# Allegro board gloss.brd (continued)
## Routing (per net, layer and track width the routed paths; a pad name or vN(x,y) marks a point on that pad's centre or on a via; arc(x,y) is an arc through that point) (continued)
MEMORY.RA12: length 159.2
  TOP w0.15: 115.23,90.16 115.23,89.87 115.08,89.72 U21.19 ; 115.23,90.16 115.23,90.81 115.53,91.1 117.48,91.1 118.55,92.17 118.55,97.7 115.22,101.03 115.22,101.77 ; 115.23,90.16 115.23,90.91 115.12,90.8 115.12,86.3 116.49,84.94 116.49,81.44 116.39,81.34 116.39,78.79 114.48,76.89 U20.19 ; U23.19 114.48,113.17 ; 114.48,113.17 115,112.65 115,106.97 115.12,106.86 115.12,105.54 115.22,105.44 115.22,103.38 115.12,103.28 115.12,101.87 115.22,101.77 ; 114.48,113.17 114.19,112.87 113.35,112.87 112.58,113.64 112.58,116.57 111.58,117.57 103.79,117.57 102.42,116.2 102.42,113.8 99.98,111.36 v1(95.48,111.36) ; 91,100.07 91,101.03 ; 91,100.07 v1(90.08,100.07) ; 91,100.07 91,93.97 91.12,93.86 91.12,91.38 90.48,90.75 U17.19 90.48,83.03 v1(90.92,82.6) ; 91,101.03 90.48,101.56 U18.19 ; 91,101.03 93.45,101.03 93.65,101.23 93.65,105.71 94.44,106.5 94.44,110.63 v1(93.71,111.36) 92.9,111.36 90.48,113.77 U19.19 ; 115.22,101.77 114.94,101.77 U22.19 ; v1(89.45,82.6) 89.45,81.78 89.73,81.5 89.73,76.37 89.89,76.22 U16.19 ; v1(63.81,99.11) 64.56,98.36 66.85,98.36 67.34,97.87 67.34,97.08 66.72,96.46 U5.62
  BOTTOM w0.15: v1(63.81,99.11) 84.52,99.11 85.47,100.07 v1(90.08,100.07) ; v1(95.48,111.36) v1(93.71,111.36) ; v1(89.45,82.6) v1(90.92,82.6)
MEMORY.RA13: length 180.9
  TOP w0.15: 117.55,87.94 118.85,89.24 118.85,102.05 117.2,103.7 116.49,103.7 ; 117.55,87.94 116.26,87.94 115.75,88.44 U21.18 ; 117.55,87.94 117.55,78.67 115.75,76.89 U20.18 ; 92.49,86.57 92.91,86.57 93.55,87.2 93.55,100.3 ; 92.49,86.57 92.39,86.47 92.39,78.72 92.5,78.62 92.5,77.62 91.75,76.89 U16.18 ; 92.49,86.57 92.15,86.57 91.75,86.97 U17.18 ; 94.74,112.26 100.4,112.26 101.15,113.01 101.15,116.3 101.03,116.41 101.03,117.16 102.18,118.3 113.98,118.3 115.75,116.53 U23.18 115.75,111.35 116.49,110.62 116.49,106.94 116.39,106.84 116.39,103.8 116.49,103.7 ; 94.74,112.26 94.74,105.35 94.44,105.06 94.44,101.2 93.55,100.3 ; 94.74,112.26 93.41,112.26 91.75,113.91 U19.18 ; U18.18 92.36,102.22 92.49,102.35 92.49,103.41 v1(92.92,103.84) ; 116.49,103.7 116.49,102.35 116.36,102.22 U22.18 ; 93.55,100.3 v1(92.79,100.3) ; U5.61 64.13,95.19 62.73,96.59 62.73,103.62 62.22,104.13 v1(61.17,104.13)
  BOTTOM w0.15: v1(92.92,103.84) 92.92,100.43 v1(92.79,100.3) 92.79,97.37 92.15,96.73 91.45,96.73 90.81,97.37 90.81,100.41 88.66,102.57 61.68,102.57 61.17,103.08 v1(61.17,104.13)
MEMORY.RA14: length 163.2
  TOP w0.15: v1(91.75,103.91) U19.15 91.75,106.17 93.29,107.7 v1(93.71,107.7) ; U21.15 v1(115.75,82.73) ; U16.15 v1(91.75,68.4) ; U23.15 v1(115.75,107.25) ; v1(62,103.31) 62,96.08 64.16,93.92 U5.60 ; v1(91.75,97.46) U18.15 91.75,90.97 91.12,90.33 91.12,85.77 91.75,85.14 U17.15 v1(91.75,78.16) ; U20.15 v1(115.75,68.4) ; U22.15 v1(115.75,94.4)
  BOTTOM w0.15: 91.75,103.11 v1(91.75,103.91) ; 91.75,103.11 v1(91.75,97.46) ; 91.75,103.11 62.2,103.11 v1(62,103.31) ; v1(115.75,68.4) v1(115.75,82.73) v1(115.75,94.4) v1(115.75,107.25) 115.75,112.68 114.1,114.33 98.18,114.33 97.68,113.83 97.68,110.36 95.01,107.7 v1(93.71,107.7) ; v1(91.75,78.16) v1(91.75,68.4)
MEMORY.RA15: length 196.8
  TOP w0.15: v1(73.26,72.23) 81.38,72.23 85.19,68.42 85.19,67.97 ; 113.97,66.63 113.97,65.3 111.47,62.8 87.68,62.8 84.77,65.7 84.77,67.97 85.19,67.97 ; 113.97,66.63 114.34,66.63 U20.14 ; 113.97,66.63 113.97,65.59 113.85,65.7 113.85,77.3 113.97,77.41 113.97,78.44 114.48,78.96 U21.14 v1(114.48,81.8) 114.48,86.95 113.97,87.47 113.97,88.53 113.85,88.64 113.85,90.83 114.48,91.47 U22.14 ; U19.14 91.08,105.78 91.11,105.8 v1(91.11,107.4) ; U5.58 v1(60.31,91.38) ; v1(108.63,108.56) 112.97,108.56 114.48,107.05 U23.14 v1(114.48,103.91) ; 85.19,67.97 85.8,67.97 86.04,67.72 86.04,65.81 86.34,65.51 89.88,65.51 90.48,66.12 U16.14 v1(90.48,69.27) ; v1(90.48,78.16) U17.14 90.48,81.72 90.19,82.02 90.19,86.19 89.85,86.52 89.85,90.86 90.48,91.49 U18.14
  BOTTOM w0.15: v1(91.11,107.4) 91.84,106.67 101.48,106.67 103.38,108.56 v1(108.63,108.56) ; v1(73.26,72.23) 73.26,78.3 67.16,84.4 66.53,84.4 60.31,90.62 v1(60.31,91.38) ; v1(90.48,69.27) v1(90.48,78.16) ; v1(114.48,103.91) v1(114.48,81.8)
MEMORY.RCS0: length 54.5
  TOP w0.15: U5.51 v1(61.66,81.71) ; U17.6 v1(80.33,81.4) ; v1(71.63,65.35) 80.19,65.35 80.33,65.48 U16.6 v1(80.33,69.77)
  BOTTOM w0.15: v1(80.33,69.77) 80.33,70.58 79.81,71.1 79.81,80.06 80.33,80.58 v1(80.33,81.4) ; v1(61.66,81.71) 68.83,81.71 71.63,78.92 v1(71.63,65.35)
MEMORY.RCS1: length 41.2
  TOP w0.15: U19.6 80.33,104.52 79.22,103.41 78.56,103.41 78.31,103.15 78.31,100.69 78.16,100.54 78.16,97.34 v1(80.33,95.17) U18.6 ; v1(62.51,89.81) 60.39,87.69 U5.50
  BOTTOM w0.15: v1(80.33,95.17) 67.87,95.17 v1(62.51,89.81)
MEMORY.RCS2: length 79.7
  TOP w0.15: v1(95.25,64.13) 95.25,66.88 99.44,71.07 102.13,71.07 v1(102.86,70.34) 104.33,68.87 U20.6 ; U21.6 v1(104.33,81.9) ; U5.49 v1(59.12,80.85)
  BOTTOM w0.15: v1(59.12,80.85) 70.8,69.16 70.8,65.02 71.69,64.13 v1(95.25,64.13) ; v1(104.33,81.9) 102.86,80.43 v1(102.86,70.34)
MEMORY.RCS3: length 65.8
  TOP w0.15: U22.6 104.33,94.94 v1(104.13,95.13) 105.17,96.17 105.17,99.67 105.06,99.79 105.06,101.06 104.96,101.16 104.96,103.44 104.33,104.07 U23.6 ; U5.48 57.85,86.34 62.16,90.65 v1(68.87,90.65)
  BOTTOM w0.15: v1(68.87,90.65) 94.74,90.65 97.4,93.31 97.4,94.11 98.42,95.13 v1(104.13,95.13)
MEMORY.RD0: length 187.2
  TOP w0.15: v1(92.49,94.4) v1(92.49,87.6) ; v1(101.98,68.7) 102.79,68.7 103.69,67.8 103.69,65.72 103.79,65.62 103.79,65.59 104.09,65.59 ; U18.7 v1(81.59,95.22) ; v1(59.36,93.15) 56.58,95.92 U5.81 ; U22.7 v1(105.59,94.4) ; v1(84.15,64.86) 83.58,64.29 81.87,64.29 81.59,64.56 ; 81.59,64.56 U16.7 ; 81.59,64.56 71.34,64.56 70.59,65.31 70.59,68.7 v1(72.36,70.46) ; 104.09,65.59 104.09,64.92 103.29,64.13 v1(99.11,64.13) ; 104.09,65.59 104.8,65.59 105.59,66.4 U20.7
  BOTTOM w0.15: v1(105.59,94.4) 100.63,89.44 83.91,89.44 82.13,87.66 82.13,86.92 82.53,86.53 92.49,86.53 ; v1(81.59,95.22) 81.59,94.41 82.34,93.67 91.75,93.67 v1(92.49,94.4) ; v1(84.15,64.86) 98.38,64.86 v1(99.11,64.13) ; v1(101.98,68.7) 101.98,83.1 98.55,86.53 92.49,86.53 ; v1(59.36,93.15) 59.36,91.04 66.6,83.8 67.28,83.8 72.36,78.72 v1(72.36,70.46) ; 92.49,86.53 v1(92.49,87.6)
MEMORY.RD1: length 201.1
  TOP w0.15: v1(55.31,95.96) U5.82 ; U22.10 109.41,93.44 111.09,95.13 v1(117.52,95.13) ; v1(84.99,95.22) 85.41,94.81 U18.10 ; U16.10 85.41,65.56 87.56,63.4 108.39,63.4 v1(109.41,64.41) U20.10
  BOTTOM w0.15: v1(84.99,95.22) 84.26,95.96 58.32,95.96 ; 58.32,95.96 v1(55.31,95.96) ; 58.32,95.96 58.32,80.52 70.2,68.64 70.2,65.15 71.6,63.75 86.59,63.75 86.94,63.4 108.39,63.4 v1(109.41,64.41) 113.97,64.41 117.52,67.97 v1(117.52,95.13)
MEMORY.RD2: length 166.6
  TOP w0.15: U18.23 v1(85.41,103.91) ; v1(61.66,79.35) 59.47,79.35 57.22,81.61 57.22,86.13 57.31,86.23 57.31,87.29 54.04,90.56 v1(54.04,103.4) U5.83 ; 80.1,73.23 79.85,72.97 74.55,72.97 69.59,77.92 v1(69.59,79.35) ; 80.1,73.23 107.08,73.23 109.41,75.56 U20.23 ; 80.1,73.23 79.69,73.64 79.69,77.16 79.93,77.41 84.6,77.41 85.41,76.61 U16.23 ; U22.23 v1(109.41,100.6)
  BOTTOM w0.15: v1(61.66,79.35) v1(69.59,79.35) ; v1(109.41,100.6) 109.41,99.79 108.58,98.97 97.3,98.97 94.25,102.02 94.25,103.63 93.24,104.65 85.41,104.65 ; 85.41,104.65 85.19,104.86 55.51,104.86 v1(54.04,103.4) ; 85.41,104.65 v1(85.41,103.91)
MEMORY.RD3: length 236.3
  TOP w0.15: U16.26 81.59,74.42 82.48,73.53 104.52,73.53 v1(105.59,74.6) U20.26 ; U5.84 v1(52.77,102.57) ; U22.26 105.59,103.64 104.96,104.27 104.96,106.84 104.86,106.93 104.86,107.82 106.64,109.6 110.48,109.6 111.19,110.31 v1(111.19,116.84) ; U18.26 v1(81.59,100.22)
  BOTTOM w0.15: 113.95,117.14 113.65,116.84 v1(111.19,116.84) ; 113.95,117.14 116.79,114.3 116.79,67.7 116.15,67.06 115.49,67.06 111.55,71 111.55,71.27 107.49,75.33 106.33,75.33 v1(105.59,74.6) ; 113.95,117.14 113.95,117.91 113.55,118.3 57.45,118.3 50.47,111.32 50.47,104.88 v1(52.77,102.57) 53.58,102.57 53.88,102.27 79.55,102.27 v1(81.59,100.22)
MEMORY.RD4: length 126.4
  TOP w0.15: v1(105.6,107.4) U23.7 105.59,104.52 106.11,104 106.11,103.41 106.23,103.3 106.23,96.17 104.86,94.81 104.86,93.94 104.96,93.84 104.96,88.55 105.17,88.34 105.17,82.93 ; U17.7 81.59,78.52 82.41,77.7 85.54,77.7 86.04,77.21 86.04,75.14 85.92,75.03 85.92,74.27 86.32,73.87 102.31,73.87 103.69,75.25 103.69,77.3 103.58,77.41 103.58,79.09 103.69,79.2 103.69,81.36 103.58,81.47 103.58,82.3 104.21,82.93 105.17,82.93 ; 105.17,82.93 105.59,82.51 U21.7 ; U19.7 v1(81.59,107.4) ; U5.1 v1(51.5,111.31)
  BOTTOM w0.15: v1(51.5,111.31) 52.63,112.43 75.16,112.43 79.16,108.43 80.56,108.43 v1(81.59,107.4) 82.93,106.06 104.26,106.06 v1(105.6,107.4)
MEMORY.RD5: length 155.4
  TOP w0.15: v1(66.27,115.93) 51.93,115.93 50.23,114.22 U5.2 ; U19.10 85.41,107.4 v1(85.41,107.4) ; U17.10 v1(85.41,81.4) ; U21.10 v1(109.41,78.66) ; v1(109.35,104.16) 109.41,104.21 U23.10
  BOTTOM w0.15: v1(109.41,78.66) 108.61,79.45 105.06,79.45 ; 105.06,79.45 104.73,79.45 103.59,78.31 103.59,69.22 101.94,67.57 91.07,67.57 88.15,70.5 88.15,71.37 85.41,74.12 v1(85.41,81.4) ; 105.06,79.45 105.06,82.56 103.71,83.91 103.71,85.38 104.5,86.17 108.62,86.17 111.03,88.58 111.03,97.8 110.42,98.41 110.42,103.09 v1(109.35,104.16) 109.35,106.04 107.26,108.13 104.13,108.13 102.37,106.36 86.44,106.36 v1(85.41,107.4) 86.95,108.94 86.95,110.83 85.81,111.97 82.85,111.97 81.2,113.63 68.56,113.63 v1(66.27,115.93)
MEMORY.RD6: length 175.7
  TOP w0.15: U21.23 v1(109.41,88.1) 109.21,87.91 v1(109.21,83.02) ; U17.23 v1(85.41,87.36) ; v1(69.1,114.76) 67.2,116.66 50.74,116.66 48.96,114.88 U5.3 ; U23.23 v1(109.41,116.84) ; U19.23 v1(85.41,113.29)
  BOTTOM w0.15: v1(109.41,88.1) 108.67,88.83 86.88,88.83 v1(85.41,87.36) ; v1(69.1,114.76) 69.57,114.29 85.41,114.29 ; v1(109.21,83.02) 112.15,80.08 112.15,70.84 115.33,67.66 116.09,67.66 116.49,68.06 116.49,112.49 113.44,115.53 109.41,115.53 ; 85.41,114.29 v1(85.41,113.29) ; 85.41,114.29 94.99,114.29 96.23,115.53 109.41,115.53 ; 109.41,115.53 v1(109.41,116.84)
MEMORY.RD7: length 169.4
  TOP w0.15: v1(69.23,116.11) 68.08,117.26 50.1,117.26 47.69,114.85 U5.4 ; 106.11,89.86 105.74,89.86 U21.26 ; 106.11,89.86 106.11,90.69 106.68,91.25 108.2,91.25 108.77,91.82 108.77,93.86 111.53,96.62 v1(112.77,96.62) ; 106.11,89.86 106.11,90.91 106.23,90.8 106.23,88.64 106.11,88.53 v1(106.11,78.42) ; U17.26 81.59,87.36 80.33,86.09 v1(79.59,86.09) ; v1(105.59,116.84) U23.26 v1(105.59,113.43) ; v1(81.59,116.84) U19.26
  BOTTOM w0.15: 81.59,116.11 104.86,116.11 v1(105.59,116.84) ; 81.59,116.11 v1(81.59,116.84) ; 81.59,116.11 v1(69.23,116.11) ; v1(106.11,78.42) 103.89,76.2 103.89,69.05 102.11,67.27 90.85,67.27 87.55,70.58 87.55,71.32 85.9,72.97 83.09,72.97 81.57,74.5 81.57,82.27 79.59,84.25 v1(79.59,86.09) ; v1(112.77,96.62) 112.77,112.54 111.88,113.43 v1(105.59,113.43)
MEMORY.RWE: length 175.1
  TOP w0.15: U16.11 86.67,68.05 90,71.37 v1(93.61,71.37) 103.73,71.37 104.33,70.77 110.38,70.77 110.67,70.47 ; 111.41,92.33 111.13,92.33 U22.11 ; 111.41,92.33 111.31,92.43 111.31,93.74 111.53,93.97 114.88,93.97 115.12,93.72 115.12,91.73 115.45,91.4 117.27,91.4 118.25,92.39 118.25,95.55 115.84,97.96 112.31,97.96 110.16,100.12 110.16,101.03 110.04,101.14 110.04,103.63 110.67,104.27 U23.11 ; 111.41,92.33 111.41,90.88 111.31,90.78 111.31,86.43 112.43,85.31 112.43,82.48 111.19,81.25 111.19,80.42 ; U21.11 110.82,80.42 111.19,80.42 ; 111.19,80.42 111.31,80.31 111.31,71.1 110.67,70.47 ; U19.11 86.67,104.27 87.19,103.75 87.19,103.41 87.31,103.3 87.31,101.18 85.54,99.42 79.39,99.42 78.75,98.78 78.75,98.04 80.03,96.77 86.91,96.77 87.59,97.44 88.21,97.44 88.72,96.93 88.72,94.66 88.32,94.27 87.5,94.27 86.67,93.44 U18.11 86.67,90.97 87.31,90.33 87.31,88.14 87.04,87.88 v1(87.04,81.7) 86.67,81.33 U17.11 ; 110.67,70.47 U20.11 ; U5.56 v1(70.52,88.84)
  BOTTOM w0.15: v1(70.52,88.84) 79.83,88.84 81.36,87.32 81.36,86.69 82.37,85.67 86.46,85.67 87.34,84.8 ; 87.34,84.8 87.04,84.5 v1(87.04,81.7) ; 87.34,84.8 89.8,84.8 93.61,80.99 v1(93.61,71.37)
MRD: length 38.8
  BOTTOM w0.15: J1.46 13.17,53.52 13.43,53.78 38.73,53.78 43.41,58.46 43.41,60.23 U2.9
MWR: length 44.6
  BOTTOM w0.15: U2.10 47.17,64.19 47.17,60.2 38.47,51.49 13.69,51.49 13.17,50.98 J1.45
N00036_DATA_DAAMP: length 38.4
  TOP w0.15: 83.41,43.17 83.74,43.5 87.08,43.5 87.23,43.66 87.23,44.6 86.44,45.41 U10.5 ; 83.41,43.17 U8.8 ; 83.41,43.17 83.41,41.42 83.27,41.27 81.14,41.27 80.91,41.04 80.91,39.36 ; U8.5 80.91,39.36 ; 80.91,39.36 80.91,37.61 81.05,37.46 84.62,37.46 84.95,37.13 v1(85.76,37.13) 92.4,30.5 L4.2
  BOTTOM w0.15: R7.1 86.83,37 86.83,37.13 ; R6.1 87.44,39.5 86.83,38.88 86.83,37.13 ; 86.83,37.13 v1(85.76,37.13)
N00036_DATA_DAAMP1: length 35.5
  TOP w0.15: L6.2 96.16,11.85 96.16,13.21 95.01,14.35 92.11,14.35 87.25,19.21 v1(84.45,19.21) 83.71,19.21 83.71,19.44 ; U11.5 83.71,19.44 ; 83.71,19.44 83.71,23.25 ; U11.8 83.71,23.25 ; 83.71,23.25 83.71,24.47 84.73,25.48 U13.5
  BOTTOM w0.15: R9.1 86.78,17.08 86.53,17.33 86.53,19.21 ; R8.1 86.78,19.58 86.53,19.32 86.53,19.21 ; 86.53,19.21 v1(84.45,19.21)
N00038_DATA_DAAMP: length 24.8
  TOP w0.15: v1(83.85,39.7) 83.85,38.39 ; 83.85,38.39 85.69,38.39 91.08,33 L3.2 ; 83.85,38.39 83.55,38.09 U8.4
  BOTTOM w0.15: v1(83.85,39.7) 81.17,42.38 77.51,42.38 77.5,42.37 C8.1
N00038_DATA_DAAMP1: length 24.4
  TOP w0.15: v1(79.33,18.17) U11.4 85.15,18.17 90.25,13.08 L5.2
  BOTTOM w0.15: C11.1 77.5,22.44 77.51,22.45 78.74,22.45 79.33,21.87 v1(79.33,18.17)
N00044_DATA_DAAMP: length 6.6
  TOP w0.15: U10.1 92.86,41.59 94.52,39.93 U9.2
N00044_DATA_DAAMP1: length 6.6
  TOP w0.15: U13.1 92.86,21.67 94.52,20.01 96.93,20.01
N00060_DATA_DAAMP: length 23.9
  TOP w0.15: v1(99,34.52) 93.04,34.52 86.93,40.64 U8.6
  BOTTOM w0.15: U9.3 v1(99,34.52)
N00060_DATA_DAAMP1: length 26.5
  TOP w0.15: U11.6 v1(80.35,20.71)
  BOTTOM w0.15: U12.3 97,17.15 95.11,17.15 91.36,13.4 86.64,13.4 80.35,19.7 v1(80.35,20.71)
N282866_DATA_DAAMP: length 6.7
  TOP w0.15: U10.8 v1(88.84,41.59)
  BOTTOM w0.15: v1(88.84,41.59) 89.65,41.59 90.22,41.02 90.22,39.6 90.12,39.5 R6.2
N282866_DATA_DAAMP1: length 6.7
  TOP w0.15: U13.8 v1(88.84,21.67)
  BOTTOM w0.15: v1(88.84,21.67) 89.65,21.67 90.22,21.1 90.22,19.68 90.12,19.58 R8.2
N282912_DATA_DAAMP: length 9.3
  TOP w0.15: U10.2 v1(92.62,42.87)
  BOTTOM w0.15: R7.2 90.22,37 92.62,39.4 v1(92.62,42.87)
N282912_DATA_DAAMP1: length 9.3
  TOP w0.15: U13.2 v1(92.62,22.94)
  BOTTOM w0.15: R9.2 90.22,17.08 92.62,19.48 v1(92.62,22.94)
NCS: length 12.8
  TOP w0.15: U7.4 36.13,113.25 U5.11
OE: length 27
  TOP w0.15: U7.3 27.93,103.58 26.02,101.67 26.02,98.32 36.24,88.11 38.51,88.11 38.84,87.77 38.84,86.92 38.23,86.3 U5.32
OUTA: length 15.7
  TOP w0.15: L1.1 98.37,35.5 103.37,40.5 103.37,42.99 102.3,44.07 U9.6
OUTB: length 15.7
  TOP w0.15: U12.6 102.3,24.14 103.37,23.07 103.37,20.58 98.37,15.58 L2.1
Q0: length 6.5
  TOP w0.15: R1.1 77.78,60 77.6,60.17 U6.18
Q1: length 6.4
  TOP w0.15: U6.16 73.41,57.63 73.55,57.5 R2.1
Q2: length 6.4
  TOP w0.15: U6.14 73.41,55.09 73.51,55 R3.1
Q3: length 6.4
  TOP w0.15: U6.12 77.81,52.55 77.86,52.5 R4.1
RDY: length 50.6
  TOP w0.15: U2.23 39.55,46.22 39.55,55.35 38.27,56.62 v1(36.26,56.62)
  BOTTOM w0.15: v1(36.26,56.62) 36.26,55.11 35.86,54.72 11.91,54.72 10.77,55.86 10.77,62.37 J1.50
RESET: length 69.8
  TOP w0.15: U5.15 33.39,107.89 30.66,105.16 v1(14.59,105.16)
  BOTTOM w0.15: J1.53 11.07,72.31 7.04,72.31 5.39,73.96 5.39,91.54 6.78,92.93 12.31,92.93 14.59,95.22 v1(14.59,105.16)
SEL: length 46.6
  TOP w0.15: U5.13 39.4,110.43 40.28,109.54 v1(40.28,96.55)
  BOTTOM w0.15: U2.14 37.49,68.78 37.49,93.75 v1(40.28,96.55)
V+12: length 178
  TOP w0.15: U13.4 v1(93.35,25.48) ; U10.4 92.27,45.41 92.48,45.62 92.48,46.07 ; J1.64 J1.63 17.05,96.7 21.11,92.64 30.42,92.64 33.59,89.46 33.59,68.87 38.22,64.24 64.58,64.24 67.06,61.76 67.06,54.64 71.89,49.81 88.75,49.81 92.48,46.07 ; 92.48,46.07 97.85,46.07 U9.7
  BOTTOM w0.15: U9.7 97.65,46.27 97.45,46.27 93.35,42.17 93.35,34.5 ; U12.7 97.78,26.22 93.35,26.22 ; 93.35,26.22 v1(93.35,25.48) 93.35,16.61 91.32,14.58 C12.1 ; 93.35,26.22 93.35,34.5 ; C9.1 93.35,34.5
VCLKA: length 76.7
  TOP w0.15: v1(61.66,72.65) 50.58,72.65 40.07,83.16 U5.34 ; U14.11 68.2,34.28 67.41,35.09 67.41,46.17 67.91,46.68 v1(71.51,46.68) 72.49,46.68 72.84,46.33 U8.11
  BOTTOM w0.15: v1(61.66,72.65) 68.44,65.87 68.44,49.75 v1(71.51,46.68)
VCLKC: length 92.7
  TOP w0.15: U15.11 67.33,14.36 67.31,14.38 67.31,28.19 67.84,28.71 v1(67.84,29.53) 69.72,29.53 72.84,26.4 U11.11
  BOTTOM w0.15: R5.2 50.25,89 57.61,81.63 57.61,73.75 67.84,63.52 v1(67.84,29.53)
VD0: length 91.6
  TOP w0.15: U14.2 v1(52.29,44.45) ; U5.39 v1(46.42,77.88) ; U15.2 57.98,24.52 57.47,25.03 v1(57.47,29) ; U6.2 v1(48.51,61.45)
  BOTTOM w0.15: 52.29,29 v1(52.29,44.45) 48.51,48.23 v1(48.51,61.45) 48.51,75.79 v1(46.42,77.88) ; 52.29,29 R13.2 ; 52.29,29 v1(57.47,29)
VD1: length 88.4
  TOP w0.15: v1(56.73,26.02) 56.73,24.52 58,23.25 U15.3 ; v1(53.13,74.88) 47.69,80.32 U5.40 ; U14.3 56.35,43.17 v1(56.14,42.97) ; U6.3 v1(53.13,60.17)
  BOTTOM w0.15: v1(53.13,74.88) v1(53.13,60.17) 53.13,45.98 v1(56.14,42.97) 56.14,32.93 58.93,30.14 58.93,26.42 58.54,26.02 v1(56.73,26.02) 56.26,26.5 R17.2
VD2: length 84.8
  TOP w0.15: v1(56,24) 56,23.19 57.2,21.98 U15.4 ; v1(57.65,40.01) 57.65,40.94 58.62,41.91 U14.4 ; v1(53.96,76.77) 48.96,81.77 U5.41 ; U6.4 v1(58.14,58.91)
  BOTTOM w0.15: R12.2 v1(56,24) 56.95,24 59.23,26.29 59.23,33.71 56.92,36.03 56.92,39.27 v1(57.65,40.01) 58.14,40.5 v1(58.14,58.91) 53.96,63.09 v1(53.96,76.77)
VD3: length 115.4
  TOP w0.15: U15.5 v1(56.14,20.71) ; v1(53.64,21.5) 53.64,17.82 57.84,13.63 61.37,13.63 65.56,17.82 v1(65.56,40.63) 65.56,56.25 64.17,57.63 U6.5 v1(50.23,57.63) ; U14.5 v1(63.36,40.64) ; U5.42 v1(50.23,82.81)
  BOTTOM w0.15: v1(63.36,40.64) 63.94,41.21 64.98,41.21 v1(65.56,40.63) ; v1(50.23,57.63) v1(50.23,82.81) ; v1(56.14,20.71) 55.36,21.5 v1(53.64,21.5) R16.2
VD4: length 91.1
  TOP w0.15: 60.9,39.36 63.21,39.36 64.09,40.25 64.09,55.56 63.3,56.37 U6.6 v1(51.5,56.37) ; 60.9,39.36 U14.6 ; 60.9,39.36 60.9,19.66 60.67,19.44 U15.6 v1(55.84,19.44) ; U5.43 v1(51.5,82.81)
  BOTTOM w0.15: R11.2 55.4,19 v1(55.84,19.44) ; v1(51.5,56.37) v1(51.5,82.81)
VD5: length 92.7
  TOP w0.15: U14.7 54.68,38.09 54.38,37.8 ; 54.38,37.8 v1(54.38,18.17) ; 54.38,37.8 51.23,40.94 51.23,54.06 v1(52.27,55.09) U6.7 ; U5.44 v1(52.77,80.42) ; U15.7 v1(55.84,18.17)
  BOTTOM w0.15: v1(52.27,55.09) 52.27,79.91 v1(52.77,80.42) ; R15.2 52.7,16.5 v1(54.38,18.17) v1(55.84,18.17)
VD6: length 86.8
  TOP w0.15: U15.8 v1(57.65,16.9) ; U6.8 v1(60.16,53.83) ; U14.8 v1(57.65,36.83) ; U5.45 v1(54.04,80.16)
  BOTTOM w0.15: v1(54.04,80.16) 54.9,79.3 54.9,68.81 60.16,63.54 v1(60.16,53.83) 60.16,37.15 59.53,36.52 ; 59.53,36.52 59.53,18.79 v1(57.65,16.9) 55.71,16.9 52.81,14 R10.2 ; 59.53,36.52 59.23,36.83 v1(57.65,36.83)
VD7: length 93.2
  TOP w0.15: U15.9 v1(56.97,15.63) 55.11,17.49 55.11,33.14 57.52,35.55 U14.9 59.8,35.55 60.59,36.36 60.59,38.5 60.36,38.73 57.83,38.73 56.92,39.64 56.92,41.29 58.17,42.54 60.37,42.54 60.9,43.07 v1(60.9,52.55) U6.9 ; U5.46 v1(55.31,82.79)
  BOTTOM w0.15: v1(56.97,15.63) 52.83,11.5 R14.2 ; v1(55.31,82.79) 55.31,71.8 60.9,66.22 v1(60.9,52.55)
VREF: length 25.9
  TOP w0.15: R18.1 104.75,10 102.5,12.25 L5.1
  BOTTOM w0.15: L5.1 103.89,14.47 103.89,31.61 L3.1
WAIT: length 53.3
  TOP w0.15: U5.33 38.8,78.33 v1(34.33,73.86)
  BOTTOM w0.15: J1.51 12.15,66.15 16.75,66.15 18.14,64.75 18.14,62.23 23.1,57.27 28.36,57.27 34.33,63.24 v1(34.33,73.86)
WSTAT: length 45.2
  TOP w0.15: U5.57 64.78,90.11 64.16,89.49 64.16,88.68 64.63,88.2 66.97,88.2 67.96,87.22 67.96,54.76 71.44,51.28 U6.11
N14843: length 2.7
  BOTTOM w0.15: R16.1 C19.1
N14849: length 2.7
  BOTTOM w0.15: R12.1 C15.1
N14853: length 2.7
  BOTTOM w0.15: R17.1 C20.1
N14855: length 2.7
  BOTTOM w0.15: R13.1 C16.1
N15143: length 2.7
  BOTTOM w0.15: R14.1 C17.1
N15151: length 2.7
  BOTTOM w0.15: R10.1 C13.1
N15155: length 2.7
  BOTTOM w0.15: R15.1 C18.1
N15161: length 2.7
  BOTTOM w0.15: R11.1 C14.1
N58063: length 4.2
  TOP w0.15: U14.19 U8.12
N58118: length 4.2
  TOP w0.15: U14.18 U8.13
N58173: length 4.2
  TOP w0.15: U14.17 U8.14
N58228: length 4.2
  TOP w0.15: U14.16 U8.15
N58283: length 4.2
  TOP w0.15: U14.15 U8.16
N58338: length 4.2
  TOP w0.15: U14.14 U8.17
N58393: length 4.2
  TOP w0.15: U14.13 U8.18
N58448: length 4.2
  TOP w0.15: U14.12 U8.19
N58834: length 4.2
  TOP w0.15: U15.19 U11.12
N58889: length 4.2
  TOP w0.15: U15.18 U11.13
N58944: length 4.2
  TOP w0.15: U15.17 U11.14
N58999: length 4.2
  TOP w0.15: U15.16 U11.15
N59054: length 4.2
  TOP w0.15: U15.15 U11.16
N59109: length 4.2
  TOP w0.15: U15.14 U11.17
N59164: length 4.2
  TOP w0.15: U15.13 U11.18
N59219: length 4.2
  TOP w0.15: U15.12 U11.19
N409523: length 6.4
  TOP w0.15: U5.37 v1(43.88,89)
  BOTTOM w0.15: R5.1 v1(43.88,89)

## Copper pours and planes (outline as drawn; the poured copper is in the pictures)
GND on GND1, GND2: 21,1.41 21,9 20.41,10.41 19,11 1.41,11 1,11.41 1,108.59 1.41,109 19,109 20.41,109.59 21,111 21,118.59 21.41,119 118.59,119 119,118.59 119,1.41 118.59,1 21.41,1 ; 2 cut-outs
VCC on VCC1, VCC2: 21,1.41 21,9 20.41,10.41 19,11 1.41,11 1,11.41 1,108.59 1.41,109 19,109 20.41,109.59 21,111 21,118.59 21.41,119 118.59,119 119,118.59 119,1.41 118.59,1 21.41,1 ; 2 cut-outs
